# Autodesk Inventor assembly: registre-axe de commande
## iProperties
Author: chr
Created: 2001-06
Part Number: registre-axe de commande
Document SubType Name: Assemblage
Designer: chr
Control State: 0
Master: False
Checked Out: False
PropertySet Name: Design Tracking Control
Shininess: 21.0
PropertySet Name: _Private Model Information
Length Units: 11272
Angle Units: 11286
Time Units: 11279
Mass Units: 11290
Length Display Precision: 3
Angle Display Precision: 2
Compacted: False
Density: 0.0
Volumn: 0.0
Area: 0.0
PropertySet Name: Model Information
